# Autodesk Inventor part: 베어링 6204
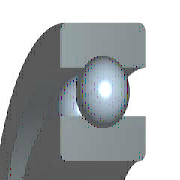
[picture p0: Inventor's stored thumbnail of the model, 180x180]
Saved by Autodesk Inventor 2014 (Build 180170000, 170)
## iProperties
Created: 2012-02
Part Number: 베어링 6204
Material: 강철, 연강
Description: 깊은 그루브 볼 베어링
Document SubType Name: Modeling
Standard: KS B 2023
Designer: mduedu
Standards Organization: KS
Language: ko-KR
Size Designation: 6204 - 20 x 47 x 14
Categories: <MemberInstance><Categories><Category DisplayName="샤프트 부품" InternalName="7f7aeb1f-a693-4053-b835-cee3144e0d98" Mnemonic="SHFT"><Category DisplayName="베어링" Inter
Density: 1 g/cm^3
Appearance: Yellow
IsCustomPart: 1
Author: mduedu
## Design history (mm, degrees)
sketch "스케치" dims "d0" = 7.02 (= -0.26 x WD + 0.26 x BD)
  geometry: L1 (3.49, 16.75)-(10.51, 16.75); L2 (7, 16.75)-(7, 13.24); L3 (7, 16.75)-(7, 20.26); L4 (4.392, 14.401)-(0, 14.401); L5 (0, 10)-(14, 10); L6 (4.392, 19.099)-(0, 19.099); L7 (0, 23.5)-(14, 23.5); L8 (14, 10)-(14, 14.401); L9 (9.608, 14.401)-(14, 14.401); L10 (9.608, 19.099)-(14, 19.099); L11 (14, 23.5)-(14, 19.099); L12 (-1.4, 0)-(8.4, 0) reference; L13 (0, -0.3)-(0, 5.3) reference
  constraints: 22 end point, 4 point on line, 2 collinear, 2 perpendicular, 2 symmetric about line, 1 midpoint, 1 parallel, 14 other
  dimensions: "d9" = 20 diameter of L5 L12 (= WD); "d11" = 47 diameter of L7 L12 (= BD); "d12" = 14 distance between parallel lines of L8 L13 (= KB); "d13" = 28.802 diameter of L9 L12 (= 0.326 x BD + 0.674 x WD)
revolve "본체" stored, may be unused: angle "d6" = 90 deg
revolve "볼" stored, may be unused: angle "d7" = 90 deg
pattern_circular "IDS_ARRAYBALL[SIMPL:T]" dims angle "d3" = 360 deg
body "Solid1"
fillet "모깎기1" dims "d1" = 1 (= KRS)
other parameters: "WD" = 20 [user parameter; used in 5 equation terms], "BD" = 47 [user parameter; used in 5 equation terms], "KB" = 14 [user parameter; used in 1 equation term], "KRS" = 1 [user parameter; used in 1 equation term], "d4" = 0, "d5" = 0, "d8" = 0, "d14" = 0, "d15" = 0, "BBA" = 0 [user parameter], "BC0" = 6550000 [user parameter], "BC" = 1.27e+07 [user parameter], "BR" = 23.5 (= 0.5 x BD) [user parameter]
